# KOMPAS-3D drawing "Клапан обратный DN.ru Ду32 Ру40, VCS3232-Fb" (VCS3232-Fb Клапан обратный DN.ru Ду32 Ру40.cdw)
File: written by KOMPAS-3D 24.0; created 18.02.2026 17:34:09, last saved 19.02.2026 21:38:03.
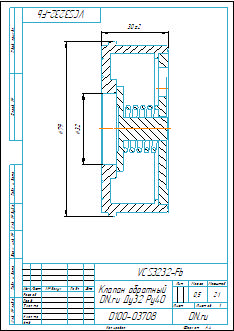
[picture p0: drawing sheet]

Document properties: v313: 1; D: 58; d: 20; a: 1; L: 28; Артикул: D100-03708; Автор: R2D2; Форматы листов документа: A4; Полное имя файла: VCS3232-Fb Клапан обратный DN.ru Ду32 Ру40.m3d; Масса: 0.5; Наименование: Клапан обратный DN.ru Ду32 Ру40; Количество листов документа: 1; Примечание: D100-03708

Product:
- Body: Тело 1  | qty 1
    Масса: 0.328859
- Body: Тело 2  | qty 1
    Масса: 0.117367
- Part/product: Клапан обратный DN.ru Ду32 Ру40  | designation VCS3232-Fb
    Масса: 0.5
    Примечание: D100-03708
    additional columns: 1; D100-03708

Views: Вид 1, Местный разрез 1, Справа
Referenced files in E:\Работа\Зайцев\VCS3232-Fb Клапан обратный DN.ru Ду15-100\DN32\: VCS3232-Fb Клапан обратный DN.ru Ду32 Ру40.m3d
Referenced files in E:\Работа\Зайцев\VCS3232-Fb Клапан обратный DN.ru Ду15-100\DN25\: VCS3232-Fb Клапан обратный DN.ru Ду25 Ру40.m3d
Referenced files in E:\Работа\Зайцев\Для компаса\: чертеж DN.ru.cdt
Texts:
  VCS3232-Fb
  чертеж DN.ru.cdt
  Клапан обратный
  DN.ru Ду32 Ру40
  prop
  Клапан обратный DN.ru Ду32 Ру40
  VCS3232-Fb Клапан обратный DN.ru Ду32 Ру40
Dimensions and other numbers on the sheet: 0; 3; 2; 4; 30±2; 79; 32; 6; 2:1; 1; 0,5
